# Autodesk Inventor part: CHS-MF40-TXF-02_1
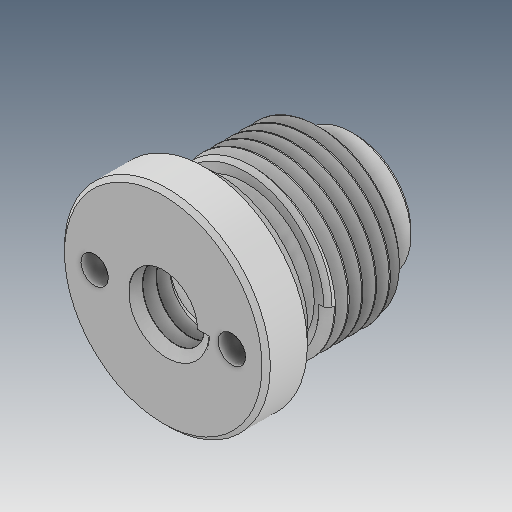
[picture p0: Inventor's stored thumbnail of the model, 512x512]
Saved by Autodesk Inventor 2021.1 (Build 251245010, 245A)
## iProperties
Created: 2019-05
Part Number: CHS-MF40-TXF-02_1
Material: Ogólny
Document SubType Name: Modeling
Designer: user
Density: 1 g/cm^3
Appearance: Domyślna
Author: user
Revision Number: ÈÎºÎ
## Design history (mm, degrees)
feature "ÊäÈë1"
node "Bryła1"
